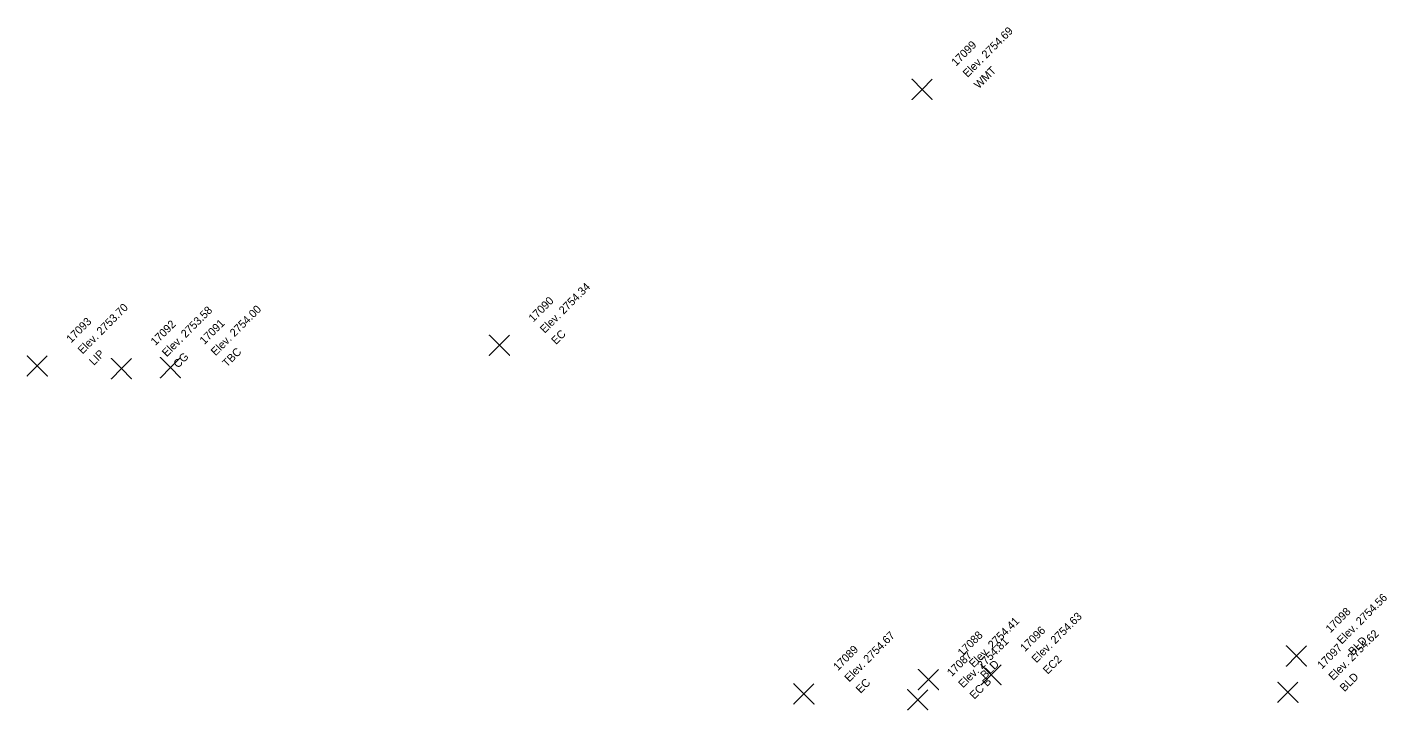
# Model space of a CAD drawing. Extents: x 2493999 to 2503109, y 700767 to 706646.
# Drawn here: x 2502327.61 to 2502348, y 704154.95 to 704165.18 of the extents above; entities that cross this region are included whole.
import ezdxf

# ---------------------------------------------------------------- set-up
doc = ezdxf.new("R2010")
doc.units = 0
doc.layers.add('ALG_CL_BLUE_Horiz', color=7, linetype='Continuous')
doc.layers.add('DES_SURFACE_Existing-Ground', color=7, linetype='Continuous')

msp = doc.modelspace()

# ---------------------------------------------------------------- linework, layer by layer
at = {"layer": 'ALG_CL_BLUE_Horiz'}
for points in [[(2502341.033, 704164.247), (2502340.883, 704164.397), (2502341.033, 704164.247), (2502340.883, 704164.097), (2502341.033, 704164.247), (2502341.183, 704164.097), (2502341.033, 704164.247), (2502341.183, 704164.397)], [(2502334.692, 704160.413), (2502334.542, 704160.563), (2502334.692, 704160.413), (2502334.542, 704160.263), (2502334.692, 704160.413), (2502334.842, 704160.263), (2502334.692, 704160.413), (2502334.842, 704160.563)], [(2502327.759, 704160.102), (2502327.609, 704160.252), (2502327.759, 704160.102), (2502327.609, 704159.952), (2502327.759, 704160.102), (2502327.909, 704159.952), (2502327.759, 704160.102), (2502327.909, 704160.252)], [(2502329.023, 704160.061), (2502328.873, 704160.211), (2502329.023, 704160.061), (2502328.873, 704159.911), (2502329.023, 704160.061), (2502329.173, 704159.911), (2502329.023, 704160.061), (2502329.173, 704160.211)], [(2502329.757, 704160.076), (2502329.607, 704160.226), (2502329.757, 704160.076), (2502329.607, 704159.926), (2502329.757, 704160.076), (2502329.907, 704159.926), (2502329.757, 704160.076), (2502329.907, 704160.226)], [(2502346.647, 704155.755), (2502346.497, 704155.905), (2502346.647, 704155.755), (2502346.497, 704155.605), (2502346.647, 704155.755), (2502346.797, 704155.605), (2502346.647, 704155.755), (2502346.797, 704155.905)], [(2502341.128, 704155.402), (2502340.978, 704155.552), (2502341.128, 704155.402), (2502340.978, 704155.252), (2502341.128, 704155.402), (2502341.278, 704155.252), (2502341.128, 704155.402), (2502341.278, 704155.552)], [(2502342.067, 704155.473), (2502341.917, 704155.623), (2502342.067, 704155.473), (2502341.917, 704155.323), (2502342.067, 704155.473), (2502342.217, 704155.323), (2502342.067, 704155.473), (2502342.217, 704155.623)], [(2502339.26, 704155.188), (2502339.11, 704155.338), (2502339.26, 704155.188), (2502339.11, 704155.038), (2502339.26, 704155.188), (2502339.41, 704155.038), (2502339.26, 704155.188), (2502339.41, 704155.338)], [(2502346.52, 704155.212), (2502346.37, 704155.362), (2502346.52, 704155.212), (2502346.37, 704155.062), (2502346.52, 704155.212), (2502346.67, 704155.062), (2502346.52, 704155.212), (2502346.67, 704155.362)], [(2502340.967, 704155.099), (2502340.817, 704155.249), (2502340.967, 704155.099), (2502340.817, 704154.949), (2502340.967, 704155.099), (2502341.117, 704154.949), (2502340.967, 704155.099), (2502341.117, 704155.249)]]:
    msp.add_lwpolyline(points, dxfattribs=at)

# ---------------------------------------------------------------- texts
at = {"layer": 'DES_SURFACE_Existing-Ground'}
for s, p in [('Elev. 2754.69', (2502341.712, 704164.417)), ('17099', (2502341.542, 704164.586)), ('WMT', (2502341.882, 704164.247)), ('Elev. 2754.34', (2502335.371, 704160.583)), ('17090', (2502335.201, 704160.752)), ('Elev. 2753.70', (2502328.438, 704160.272)), ('Elev. 2753.58', (2502329.702, 704160.231)), ('Elev. 2754.00', (2502330.436, 704160.246)), ('17093', (2502328.268, 704160.441)), ('17092', (2502329.532, 704160.4)), ('17091', (2502330.266, 704160.415)), ('EC', (2502335.541, 704160.413)), ('LIP', (2502328.608, 704160.102)), ('CG', (2502329.872, 704160.061)), ('TBC', (2502330.606, 704160.076)), ('Elev. 2754.56', (2502347.326, 704155.925)), ('Elev. 2754.63', (2502342.746, 704155.643)), ('17098', (2502347.156, 704156.094)), ('Elev. 2754.41', (2502341.807, 704155.572)), ('17096', (2502342.576, 704155.812)), ('Elev. 2754.67', (2502339.939, 704155.358)), ('Elev. 2754.81', (2502341.646, 704155.269)), ('17088', (2502341.637, 704155.741)), ('Elev. 2754.62', (2502347.199, 704155.382)), ('BLD', (2502347.496, 704155.755)), ('17089', (2502339.769, 704155.527)), ('17087', (2502341.476, 704155.438)), ('EC2', (2502342.916, 704155.473)), ('17097', (2502347.029, 704155.551)), ('BLD', (2502341.977, 704155.402)), ('EC', (2502340.109, 704155.188)), ('EC B', (2502341.816, 704155.099)), ('BLD', (2502347.369, 704155.212))]:
    msp.add_text(s, height=0.12, rotation=45, dxfattribs=at).set_placement(p)

doc.saveas('drawing.dxf')
